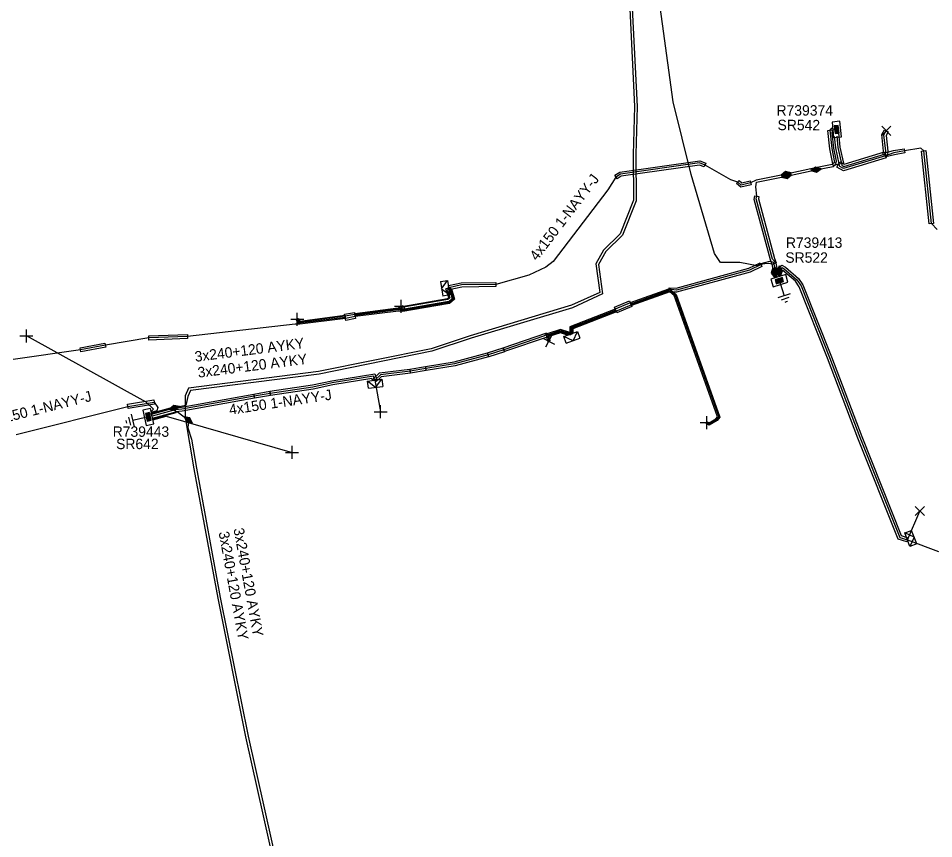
# Model space of a CAD drawing. Extents: x -540466 to -537383, y -1184038 to -1179972.
# Drawn here: x -538681.3 to -538593.3, y -1180387.6 to -1180308.7 of the extents above; entities that cross this region are included whole.
import ezdxf

# ---------------------------------------------------------------- set-up
doc = ezdxf.new("R2010")
doc.units = 0
for name, color, linetype in [('Vrstva 1', 7, 'Continuous'), ('Vrstva 14', 7, 'Continuous'), ('Vrstva 15', 7, 'Continuous'), ('Vrstva 19', 7, 'Continuous'), ('Vrstva 20', 7, 'Continuous'), ('Vrstva 28', 7, 'Continuous'), ('Vrstva 29', 7, 'Continuous'), ('Vrstva 30', 7, 'Continuous'), ('Vrstva 31', 7, 'Continuous'), ('Vrstva 34', 7, 'Continuous'), ('Vrstva 4', 7, 'Continuous'), ('Vrstva 5', 7, 'Continuous'), ('Vrstva 52', 7, 'Continuous'), ('Vrstva 59', 7, 'Continuous'), ('Vrstva 6', 7, 'Continuous'), ('Vrstva 8', 7, 'Continuous'), ('Vrstva 9', 7, 'Continuous')]:
    doc.layers.add(name, color=color, linetype=linetype)

# ---------------------------------------------------------------- blocks, each defined once
blk = doc.blocks.new('NN870')
at = {"layer": 'Vrstva 4'}
for points in [[(0, -0.251), (0.5, 0.001), (0, 0.249), (-0.5, 0.001), (0, -0.251)], [(0.37, -0.003), (0, 0.186), (-0.362, 0.001), (0, -0.188), (0.37, -0.003)], [(0.245, -0.003), (0, 0.123), (-0.252, -0.003), (0, -0.125), (0.245, -0.003)], [(0.122, -0.003), (0, 0.06), (-0.13, -0.003), (0, -0.062), (0.122, -0.003)]]:
    blk.add_lwpolyline(points, dxfattribs=at)
blk = doc.blocks.new('NN800')
at = {"layer": 'Vrstva 1'}
for points in [[(-0.442, 0.442), (0.442, -0.442)], [(-0.442, -0.442), (0.442, 0.442)]]:
    blk.add_lwpolyline(points, dxfattribs=at)
blk = doc.blocks.new('NN620')
at = {"layer": 'Vrstva 8'}
for points in [[(0.752, 0.004), (-0.748, 0.004)], [(-0.748, 0.004), (-0.748, -0.746)], [(0.752, -0.746), (0.752, 0.004)], [(-0.748, -0.746), (0.752, -0.746)], [(0.368, -0.18), (-0.376, -0.18)], [(-0.376, -0.18), (-0.376, -0.558)], [(-0.376, -0.558), (0.368, -0.558)], [(0.321, -0.227), (-0.329, -0.227)], [(-0.329, -0.227), (-0.329, -0.51)], [(-0.329, -0.51), (0.321, -0.51)], [(0.274, -0.274), (-0.281, -0.274)], [(-0.281, -0.274), (-0.281, -0.463)], [(-0.281, -0.463), (0.274, -0.463)], [(0.227, -0.321), (-0.234, -0.321)], [(-0.234, -0.321), (-0.234, -0.416)], [(-0.234, -0.416), (0.227, -0.416)], [(-0.193, -0.369), (0.185, -0.369)], [(0.227, -0.416), (0.227, -0.321)], [(0.274, -0.463), (0.274, -0.274)], [(0.321, -0.51), (0.321, -0.227)], [(0.368, -0.558), (0.368, -0.18)]]:
    blk.add_lwpolyline(points, dxfattribs=at)
blk = doc.blocks.new('NN630')
at = {"layer": 'Vrstva 9'}
for points in [[(-0.003, -0.7), (-0.703, 0)], [(-0.703, -0.7), (-0.703, 0), (0.697, 0), (0.697, -0.7)], [(-0.703, -0.7), (0.697, -0.7)], [(-0.003, -0.7), (0.697, 0)]]:
    blk.add_lwpolyline(points, dxfattribs=at)
blk = doc.blocks.new('NN810')
at = {"layer": 'Vrstva 14'}
for points in [[(0.004, -0.64), (0.004, -1.89)], [(0.629, -1.89), (-0.621, -1.89)], [(0.388, -2.2), (-0.399, -2.2)], [(0.004, -2.515), (-0.124, -2.515)], [(0.137, -2.515), (0.004, -2.515)]]:
    blk.add_lwpolyline(points, dxfattribs=at)

msp = doc.modelspace()

# ---------------------------------------------------------------- linework, layer by layer
at = {"layer": 'Vrstva 20'}
for points in [[(-538602.929, -1180322.895), (-538603.274, -1180321.28), (-538603.467, -1180319.525), (-538602.473, -1180319.415), (-538602.286, -1180321.12), (-538601.951, -1180322.685)], [(-538597.657, -1180319.66), (-538597.854, -1180320.003), (-538597.689, -1180321.531), (-538597.731, -1180321.903), (-538598.129, -1180321.857), (-538598.091, -1180321.529), (-538598.266, -1180319.917), (-538598.003, -1180319.46)], [(-538597.843, -1180322.167), (-538601.957, -1180323.415), (-538602.59, -1180323.05), (-538602.29, -1180322.53), (-538601.883, -1180322.765), (-538598.017, -1180321.593)], [(-538596.055, -1180321.677), (-538597.057, -1180321.855), (-538597.879, -1180322.073), (-538597.981, -1180321.687), (-538597.143, -1180321.465), (-538596.125, -1180321.283)], [(-538594.041, -1180321.459), (-538593.301, -1180328.459), (-538593.699, -1180328.501), (-538594.439, -1180321.501)], [(-538615.322, -1180323.037), (-538615.793, -1180322.855), (-538623.3, -1180323.912), (-538623.714, -1180324.17), (-538623.926, -1180323.83), (-538623.44, -1180323.528), (-538615.747, -1180322.445), (-538615.178, -1180322.663)], [(-538610.827, -1180324.765), (-538611.826, -1180324.987), (-538612.232, -1180324.63), (-538611.968, -1180324.33), (-538611.714, -1180324.553), (-538610.913, -1180324.375)], [(-538610.12, -1180326.097), (-538608.577, -1180331.848), (-538608.423, -1180332.26), (-538608.797, -1180332.4), (-538608.963, -1180331.952), (-538610.521, -1180326.154), (-538610.477, -1180325.808), (-538610.083, -1180325.872)], [(-538609.781, -1180332.599), (-538610.92, -1180333.138), (-538617.986, -1180335.081), (-538618.726, -1180335.06), (-538618.714, -1180334.66), (-538618.034, -1180334.679), (-538611.06, -1180332.762), (-538609.952, -1180332.238)], [(-538595.87, -1180359.061), (-538596.691, -1180358.802), (-538600.566, -1180349.093), (-538603.476, -1180341.422), (-538606.198, -1180334.555), (-538606.57, -1180334.015), (-538607.771, -1180332.989), (-538607.835, -1180332.952), (-538608.237, -1180333.267), (-538608.483, -1180332.953), (-538607.865, -1180332.468), (-538607.529, -1180332.671), (-538606.27, -1180333.745), (-538605.842, -1180334.365), (-538603.104, -1180341.278), (-538600.194, -1180348.947), (-538596.389, -1180358.478), (-538595.75, -1180358.679)], [(-538639.787, -1180334.605), (-538639.675, -1180334.898), (-538639.436, -1180335.714), (-538639.846, -1180336.064), (-538644.323, -1180336.829), (-538644.391, -1180336.434), (-538640.022, -1180335.688), (-538639.893, -1180335.578), (-538640.055, -1180335.026), (-538640.16, -1180334.746)], [(-538635.348, -1180334.54), (-538638.638, -1180334.58), (-538639.838, -1180334.836), (-538639.922, -1180334.444), (-538638.682, -1180334.18), (-538635.352, -1180334.14)], [(-538615.04, -1180347.524), (-538614.85, -1180347.634), (-538614.206, -1180347.253), (-538614.043, -1180347.051), (-538618.205, -1180335.4), (-538618.647, -1180335.046), (-538622.327, -1180336.366), (-538622.395, -1180336.178), (-538618.609, -1180334.82), (-538618.035, -1180335.28), (-538613.817, -1180347.089), (-538614.074, -1180347.407), (-538614.85, -1180347.866), (-538615.14, -1180347.696)], [(-538644.351, -1180336.829), (-538644.752, -1180336.783), (-538648.902, -1180337.32), (-538648.928, -1180337.122), (-538644.753, -1180336.582), (-538644.329, -1180336.631)], [(-538644.274, -1180336.356), (-538644.154, -1180336.656), (-538644.526, -1180336.804), (-538644.646, -1180336.504)], [(-538622.284, -1180336.457), (-538623.734, -1180337.067), (-538623.966, -1180336.513), (-538622.516, -1180335.903)], [(-538654.355, -1180337.617), (-538654.208, -1180337.849), (-538649.868, -1180337.292), (-538649.843, -1180337.49), (-538654.309, -1180338.064), (-538654.525, -1180337.723)], [(-538649.893, -1180337.195), (-538648.953, -1180337.025), (-538648.847, -1180337.615), (-538649.787, -1180337.785)], [(-538623.776, -1180336.976), (-538627.954, -1180338.599), (-538627.965, -1180338.915), (-538628.082, -1180339.128), (-538628.258, -1180339.032), (-538628.163, -1180338.861), (-538628.15, -1180338.46), (-538623.849, -1180336.789)], [(-538668.728, -1180339.27), (-538665.008, -1180339.13), (-538664.992, -1180339.53), (-538668.712, -1180339.67)], [(-538634.664, -1180340.41), (-538630.454, -1180338.99), (-538630.326, -1180339.37), (-538634.536, -1180340.79)], [(-538628.165, -1180339.18), (-538628.475, -1180339.194), (-538629.158, -1180338.98), (-538630.254, -1180339.348), (-538630.172, -1180339.76), (-538630.368, -1180339.8), (-538630.485, -1180339.215), (-538629.16, -1180338.77), (-538628.449, -1180338.993), (-538628.175, -1180338.98)], [(-538675.308, -1180340.424), (-538672.928, -1180339.964), (-538672.852, -1180340.356), (-538675.232, -1180340.816)], [(-538642.123, -1180342.213), (-538639.363, -1180341.754), (-538636.162, -1180340.887), (-538636.058, -1180341.273), (-538639.277, -1180342.146), (-538642.057, -1180342.607)], [(-538636.171, -1180340.889), (-538634.661, -1180340.409), (-538634.539, -1180340.791), (-538636.049, -1180341.271)], [(-538647.19, -1180343.593), (-538647.266, -1180343.365), (-538651.043, -1180343.977), (-538652.924, -1180344.387), (-538657.01, -1180344.998), (-538657.07, -1180344.602), (-538652.996, -1180343.993), (-538651.117, -1180343.583), (-538646.994, -1180342.915), (-538646.81, -1180343.467)], [(-538647.139, -1180343.386), (-538646.55, -1180342.819), (-538643.624, -1180342.471), (-538643.576, -1180342.869), (-538646.37, -1180343.201), (-538646.861, -1180343.674)], [(-538643.634, -1180342.473), (-538642.124, -1180342.213), (-538642.056, -1180342.607), (-538643.566, -1180342.867)], [(-538658.633, -1180344.863), (-538657.073, -1180344.603), (-538657.007, -1180344.997), (-538658.567, -1180345.257)], [(-538670.773, -1180345.853), (-538668.233, -1180345.433), (-538668.167, -1180345.827), (-538670.707, -1180346.247)], [(-538666.215, -1180346.192), (-538665.58, -1180346.112), (-538658.635, -1180344.863), (-538658.565, -1180345.257), (-538665.52, -1180346.508), (-538666.165, -1180346.588)], [(-538666.113, -1180346.68), (-538668.323, -1180347.27), (-538668.477, -1180346.69), (-538666.267, -1180346.1)]]:
    msp.add_lwpolyline(points, close=True, dxfattribs=at)
at = {"layer": 'Vrstva 5'}
for points in [[(-538608.456, -1180333.137), (-538608.645, -1180332.221), (-538609.07, -1180332.132), (-538609.534, -1180332.261), (-538609.885, -1180332.35), (-538610.255, -1180332.554), (-538611.92, -1180332.21), (-538613.78, -1180332.23), (-538614.36, -1180331.35), (-538616.58, -1180323.75), (-538618.31, -1180316.78), (-538619.86, -1180305.5), (-538622.16, -1180288.94), (-538623.97, -1180274.81), (-538624.51, -1180268.6), (-538624.99, -1180255.53), (-538625.44, -1180243.27), (-538625.55, -1180238.05), (-538626.1, -1180237.72), (-538629.06, -1180237.61), (-538631.488, -1180237.741)], [(-538622.246, -1180307.782), (-538621.775, -1180317.229), (-538621.915, -1180321.851), (-538621.864, -1180326.284), (-538623.183, -1180329.591), (-538624.799, -1180331.176), (-538625.48, -1180332.395), (-538625.104, -1180335.245), (-538627.985, -1180336.567), (-538637.743, -1180339.499), (-538641.507, -1180340.751), (-538652.349, -1180342.954), (-538664.715, -1180344.525), (-538664.965, -1180345.087), (-538665.14, -1180345.98), (-538666.242, -1180346.197)], [(-538622.494, -1180307.819), (-538622.025, -1180317.231), (-538622.165, -1180321.849), (-538622.115, -1180326.237), (-538623.396, -1180329.449), (-538625, -1180331.023), (-538625.739, -1180332.345), (-538625.376, -1180335.095), (-538628.074, -1180336.333), (-538637.818, -1180339.261), (-538641.572, -1180340.509), (-538652.39, -1180342.707), (-538664.886, -1180344.295), (-538665.215, -1180345.034), (-538665.205, -1180347.111), (-538664.373, -1180352.042), (-538662.093, -1180364.474), (-538659.422, -1180377.806), (-538654.863, -1180398.174)], [(-538602.991, -1180319.263), (-538603.268, -1180319.503), (-538603.077, -1180321.248), (-538602.818, -1180322.606), (-538603.036, -1180322.807), (-538604.631, -1180323.102), (-538607.461, -1180323.712), (-538610.33, -1180324.302), (-538610.87, -1180324.57), (-538611.77, -1180324.77), (-538612.1, -1180324.48), (-538612.765, -1180324.279), (-538615.25, -1180322.85), (-538615.77, -1180322.65), (-538623.37, -1180323.72), (-538623.82, -1180324), (-538624.59, -1180325.24), (-538629.84, -1180332.11), (-538630.57, -1180332.67), (-538632.18, -1180333.45), (-538635.35, -1180334.34), (-538638.66, -1180334.38), (-538639.88, -1180334.64), (-538639.625, -1180334.748), (-538639.322, -1180335.748), (-538639.802, -1180336.158), (-538644.306, -1180336.927), (-538644.727, -1180336.881), (-538648.885, -1180337.419), (-538649.825, -1180337.589), (-538654.187, -1180338.149), (-538654.64, -1180338.15), (-538665, -1180339.33), (-538668.72, -1180339.47), (-538672.89, -1180340.16), (-538675.27, -1180340.62), (-538681.76, -1180341.53)], [(-538604.589, -1180323.298), (-538602.944, -1180322.993), (-538602.682, -1180322.754), (-538602.607, -1180322.485), (-538602.879, -1180321.216), (-538603.037, -1180319.756), (-538602.97, -1180319.47)], [(-538592.94, -1180329.05), (-538593.5, -1180328.48), (-538594.24, -1180321.48), (-538594.5, -1180321.24), (-538596.09, -1180321.48), (-538597.1, -1180321.66), (-538597.901, -1180321.976), (-538601.932, -1180323.198), (-538602.295, -1180322.989), (-538602.352, -1180322.726), (-538602.681, -1180321.184), (-538602.8, -1180320.099)], [(-538607.419, -1180323.908), (-538604.589, -1180323.298)], [(-538608.124, -1180333.583), (-538608.264, -1180333.083), (-538608.42, -1180332.269), (-538608.77, -1180331.9), (-538610.324, -1180326.107), (-538610.28, -1180325.84), (-538610.38, -1180324.95), (-538610.323, -1180324.505), (-538607.419, -1180323.908)], [(-538608.649, -1180333.191), (-538608.8, -1180332.393), (-538609.11, -1180332.328), (-538609.498, -1180332.359), (-538609.866, -1180332.418), (-538610.99, -1180332.95), (-538618.01, -1180334.88), (-538618.754, -1180334.766), (-538622.436, -1180336.087), (-538623.887, -1180336.697), (-538628.248, -1180338.391), (-538628.263, -1180338.875), (-538628.17, -1180339.08), (-538628.342, -1180338.921), (-538629.161, -1180338.665), (-538630.422, -1180339.085), (-538630.684, -1180339.279), (-538634.6, -1180340.6), (-538636.11, -1180341.08), (-538639.32, -1180341.95), (-538642.09, -1180342.41), (-538643.6, -1180342.67), (-538646.46, -1180343.01), (-538647, -1180343.53), (-538647.13, -1180343.14), (-538651.08, -1180343.78), (-538652.96, -1180344.19), (-538657.04, -1180344.8), (-538658.6, -1180345.06), (-538665.55, -1180346.31), (-538666.19, -1180346.39), (-538668.4, -1180346.98)], [(-538608.509, -1180333.691), (-538608.649, -1180333.191)], [(-538608.316, -1180333.637), (-538608.456, -1180333.137)], [(-538681.46, -1180348.75), (-538670.74, -1180346.05), (-538668.2, -1180345.63), (-538667.85, -1180346.16), (-538667.929, -1180346.485), (-538668.484, -1180346.636)], [(-538668.452, -1180346.787), (-538666.242, -1180346.197)], [(-538668.348, -1180347.173), (-538665.987, -1180346.543), (-538664.89, -1180347.37)], [(-538664.89, -1180347.37), (-538664.95, -1180348.12), (-538664.601, -1180349.191), (-538664.127, -1180351.999), (-538661.847, -1180364.427), (-538659.177, -1180377.754), (-538654.618, -1180398.125), (-538652.304, -1180411.589), (-538652.535, -1180413.068), (-538656.75, -1180415.515), (-538659.798, -1180416.428), (-538660.84, -1180417.51), (-538660.72, -1180418.88), (-538660.33, -1180419.61), (-538659.67, -1180421.449), (-538656.89, -1180426.4), (-538655.57, -1180428.81), (-538653.567, -1180433.007), (-538653.284, -1180436.294)]]:
    msp.add_lwpolyline(points, dxfattribs=at)
at = {"layer": 'Vrstva 52'}
for points in [[(-538602.602, -1180320.077), (-538602.483, -1180321.152), (-538602.118, -1180322.86), (-538601.908, -1180322.982), (-538597.918, -1180321.771), (-538597.89, -1180321.53), (-538598.06, -1180319.96), (-538597.83, -1180319.56)], [(-538608.066, -1180333.048), (-538608.105, -1180332.91), (-538607.85, -1180332.71), (-538607.65, -1180332.83), (-538606.42, -1180333.88), (-538606.02, -1180334.46), (-538603.29, -1180341.35), (-538600.38, -1180349.02), (-538596.54, -1180358.64), (-538595.81, -1180358.87)], [(-538607.931, -1180333.529), (-538608.066, -1180333.048)], [(-538639.88, -1180334.64), (-538639.77, -1180334.93), (-538639.55, -1180335.68), (-538639.89, -1180335.97), (-538644.34, -1180336.73), (-538644.752, -1180336.683), (-538648.915, -1180337.221), (-538649.855, -1180337.391), (-538654.259, -1180337.957), (-538654.44, -1180337.67)], [(-538639.88, -1180334.64), (-538639.999, -1180334.89), (-538639.96, -1180334.994), (-538639.778, -1180335.612), (-538639.978, -1180335.782), (-538644.416, -1180336.54), (-538644.46, -1180336.43)], [(-538628.17, -1180339.08), (-538628.064, -1180338.888), (-538628.052, -1180338.529), (-538623.813, -1180336.883), (-538622.364, -1180336.273), (-538618.628, -1180334.933), (-538618.12, -1180335.34), (-538613.93, -1180347.07), (-538614.14, -1180347.33), (-538614.85, -1180347.75), (-538615.09, -1180347.61)], [(-538668.497, -1180346.53), (-538668.272, -1180346.328), (-538668.953, -1180345.655), (-538680.471, -1180339.283)], [(-538628.17, -1180339.08), (-538628.462, -1180339.093), (-538629.159, -1180338.875), (-538630.37, -1180339.282), (-538630.27, -1180339.78)], [(-538668.32, -1180347.329), (-538667.037, -1180347.001), (-538654.949, -1180350.477)]]:
    msp.add_lwpolyline(points, dxfattribs=at)
at = {"layer": 'Vrstva 59'}
for points in [[(-538647, -1180343.53), (-538646.443, -1180346.573)], [(-538595.81, -1180358.87), (-538594.617, -1180356.112)], [(-538595.81, -1180358.87), (-538592.811, -1180359.986)]]:
    msp.add_lwpolyline(points, dxfattribs=at)

# ---------------------------------------------------------------- block references
at = {"layer": 'Vrstva 15'}
for p, rotation in [((-538608.22, -1180333.61), 17.334154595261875), ((-538668.4, -1180346.98), -77.07400083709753)]:
    msp.add_blockref('NN810', p, dxfattribs=dict(at, rotation=rotation))
at = {"layer": 'Vrstva 19'}
for p, rotation in [((-538607.461, -1180323.712), -168.38335503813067), ((-538607.419, -1180323.908), 12.164715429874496), ((-538604.592, -1180323.298), 10.491476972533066), ((-538608.649, -1180333.191), 100.40802362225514), ((-538608.456, -1180333.137), 101.17304924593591), ((-538608.066, -1180333.048), -81.18917163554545), ((-538666.242, -1180346.197), -165.05244774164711), ((-538664.91, -1180347.355), 142.97011695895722)]:
    msp.add_blockref('NN870', p, dxfattribs=dict(at, rotation=rotation))
at = {"layer": 'Vrstva 28'}
for p, rotation in [((-538602.97, -1180319.47), 95.81562652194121), ((-538608.22, -1180333.61), 17.33324262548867), ((-538668.4, -1180346.98), -77.07400083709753)]:
    msp.add_blockref('NN620', p, dxfattribs=dict(at, rotation=rotation))
at = {"layer": 'Vrstva 31'}
for p, rotation in [((-538639.88, -1180334.64), -80.9097230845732), ((-538628.17, -1180339.08), 19.65382412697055), ((-538647, -1180343.53), 6.942795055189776), ((-538595.81, -1180358.87), 110.95577677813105)]:
    msp.add_blockref('NN630', p, dxfattribs=dict(at, rotation=rotation))
at = {"layer": 'Vrstva 34'}
for p in [(-538597.83, -1180319.56), (-538594.617, -1180356.112)]:
    msp.add_blockref('NN800', p, dxfattribs=at)
for p, rotation in [((-538644.46, -1180336.43), 45), ((-538654.44, -1180337.67), 44.99999995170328), ((-538680.471, -1180339.282), 45), ((-538630.27, -1180339.78), 18.40882337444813), ((-538646.443, -1180346.573), 45), ((-538615.09, -1180347.61), 45), ((-538654.949, -1180350.477), 45.00000009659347)]:
    msp.add_blockref('NN800', p, dxfattribs=dict(at, rotation=rotation))

# ---------------------------------------------------------------- texts
at = {"layer": 'Vrstva 29'}
for s, p in [('R739374', (-538608.383, -1180318.095)), ('R739413', (-538607.479, -1180330.809)), ('R739443', (-538672.185, -1180348.975))]:
    msp.add_text(s, height=1, dxfattribs=at).set_placement(p)
at = {"layer": 'Vrstva 30'}
msp.add_text('SR542', height=1, rotation=359.728, dxfattribs=at).set_placement((-538608.286, -1180319.492))
for s, p in [('SR522', (-538607.537, -1180332.242)), ('SR642', (-538671.858, -1180350.159))]:
    msp.add_text(s, height=1, dxfattribs=at).set_placement(p)
at = {"layer": 'Vrstva 6'}
for s, rotation, p in [('4x150 1-NAYY-J', 52.613, (-538631.409, -1180332.121)), ('3x240+120 AYKY', 7.242, (-538664.237, -1180341.772)), ('3x240+120 AYKY', 7.24, (-538663.951, -1180343.296)), ('4x150 1-NAYY-J', 14.137, (-538683.795, -1180347.943)), ('4x150 1-NAYY-J', 8.503, (-538660.927, -1180346.867)), ('3x240+120 AYKY', 280.396, (-538660.582, -1180357.826)), ('3x240+120 AYKY', 280.392, (-538662.011, -1180358.159))]:
    msp.add_text(s, height=1, rotation=rotation, dxfattribs=at).set_placement(p)

doc.saveas('drawing.dxf')
